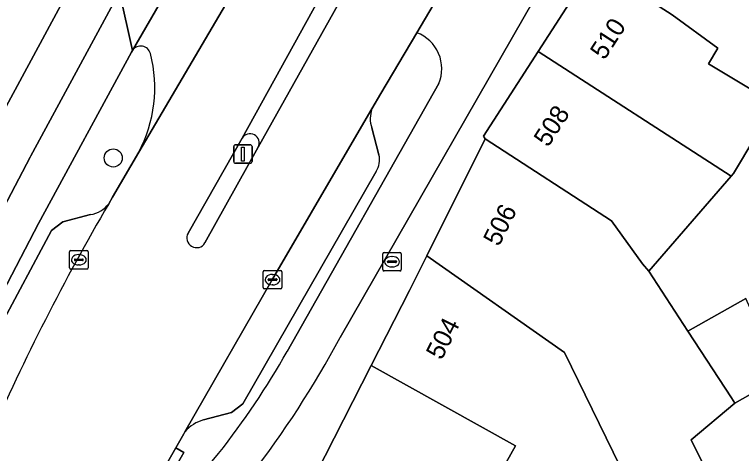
# Model space of a CAD drawing. Extents: x 162989 to 165008, y 383432 to 384338.
# Drawn here: x 163840.69 to 163879.92, y 384086.45 to 384110.15 of the extents above; entities that cross this region are included whole.
import ezdxf

# ---------------------------------------------------------------- set-up
doc = ezdxf.new("R2010")
doc.units = 0
for name, color, linetype in [('IMGEO_Boom', 7, 'Continuous'), ('IMGEO_Brandkraan', 7, 'Continuous'), ('IMGEO_Erf', 7, 'Continuous'), ('IMGEO_Fietspad_open', 7, 'Continuous'), ('IMGEO_Kolk', 7, 'Continuous'), ('IMGEO_Lichtmast', 7, 'Continuous'), ('IMGEO_Pand', 7, 'Continuous'), ('IMGEO_Pand_nummerreeks', 7, 'Continuous'), ('IMGEO_Parkeervlak_open', 7, 'Continuous'), ('IMGEO_Rijbaan_lokaal_gesloten', 7, 'Continuous'), ('IMGEO_Rijbaan_lokaal_open', 7, 'Continuous'), ('IMGEO_Verkeerseiland_open', 7, 'Continuous'), ('IMGEO_Voetpad_open', 7, 'Continuous')]:
    doc.layers.add(name, color=color, linetype=linetype)

msp = doc.modelspace()

# ---------------------------------------------------------------- linework, layer by layer
at = {"layer": 'IMGEO_Boom'}
msp.add_circle((163846.016, 384102.406), 0.489, dxfattribs=at)
at = {"layer": 'IMGEO_Brandkraan'}
for p, q in [((163860.56, 384096.377), (163860.56, 384097.229)), ((163860.635, 384097.303), (163861.487, 384097.303)), ((163861.561, 384097.229), (163861.561, 384096.377)), ((163860.819, 384096.797), (163860.819, 384096.809)), ((163861.257, 384096.76), (163860.859, 384096.76)), ((163860.862, 384096.846), (163861.26, 384096.846)), ((163861.048, 384097.083), (163861.073, 384097.083)), ((163861.303, 384096.809), (163861.303, 384096.797)), ((163861.071, 384096.523), (163861.046, 384096.523)), ((163861.487, 384096.303), (163860.635, 384096.303))]:
    msp.add_line(p, q, dxfattribs=at)
for points in [[(163860.56, 384096.377), (163860.56, 384097.229)], [(163860.635, 384097.303), (163861.487, 384097.303)], [(163861.561, 384097.229), (163861.561, 384096.377)], [(163861.487, 384096.303), (163860.635, 384096.303)]]:
    msp.add_lwpolyline(points, dxfattribs=at)
for centre, radius, start, end in [((163860.637, 384097.227), 0.0765, 91.552, 178.448), ((163860.637, 384097.227), 0.0765, 91.552, 178.448), ((163861.485, 384097.227), 0.0765, 1.552, 88.448), ((163861.485, 384097.227), 0.0765, 1.552, 88.448), ((163860.859, 384096.806), 0.0403, 85.8775, 175.7526), ((163860.856, 384096.796), 0.0366, 178.938, 274.7102), ((163861.26, 384096.803), 0.043, 264.8664, 352.4533), ((163861.264, 384096.808), 0.0386, 1.7309, 96.639), ((163860.637, 384096.379), 0.0765, 181.552, 268.448), ((163860.637, 384096.379), 0.0765, 181.552, 268.448), ((163861.485, 384096.379), 0.0765, 271.552, 358.448), ((163861.485, 384096.379), 0.0765, 271.552, 358.448)]:
    msp.add_arc(centre, radius, start, end, dxfattribs=at)
for centre, major_axis, ratio, start_param, end_param in [((163861.047, 384096.803), (-0.387, 0.002), 0.722429, 4.712389, 7.853982), ((163861.072, 384096.803), (-0.39, 0.002), 0.717154, 1.570796, 4.712389)]:
    msp.add_ellipse(centre, major_axis=major_axis, ratio=ratio, start_param=start_param, end_param=end_param, dxfattribs=at)
at = {"layer": 'IMGEO_Erf'}
for points in [[(163880.994, 384111.502), (163878.774, 384116.163), (163876.517, 384120.624), (163871.977, 384112.853), (163876.171, 384110.131), (163878.645, 384108.341), (163878.133, 384107.482), (163881.743, 384105.323), (163879.492, 384101.562), (163879.363, 384101.414), (163874.911, 384096.29), (163877.027, 384093.047), (163880.149, 384094.815)], [(163882.049, 384090.569), (163879.564, 384089.159), (163877.195, 384087.195), (163881.846, 384077.8)]]:
    msp.add_lwpolyline(points, dxfattribs=at)
at = {"layer": 'IMGEO_Fietspad_open'}
for points in [[(163858.262, 384092.719), (163870.014, 384113.204), (163876.697, 384123.662), (163880.797, 384129.62), (163884.94, 384135.639), (163890.116, 384142.65), (163886.926, 384141.93), (163880.31, 384132.681), (163877.756, 384129.074), (163877.678, 384128.954), (163873.799, 384123.243), (163873.714, 384123.118), (163868.266, 384114.374), (163867.368, 384112.852)], [(163864.451, 384112.652), (163862.396, 384109.163)], [(163835.957, 384087.299), (163841.986, 384098.868), (163846.999, 384108.122), (163847.05, 384108.21), (163846.359, 384111.374), (163841.571, 384102.524), (163841.529, 384102.444), (163833.769, 384087.617), (163830.002, 384076.297), (163825.723, 384065.107)], [(163863.578, 384106.421), (163855.398, 384091.956)]]:
    msp.add_lwpolyline(points, dxfattribs=at)
msp.add_lwpolyline([(163855.148, 384122.181), (163853.132, 384122.958), (163852.001, 384121.008), (163846.359, 384111.374), (163847.05, 384108.21)], close=True, dxfattribs=at)
for centre, radius, start, end in [((163861.689, 384107.232), 2.056, 336.7595, 69.8796), ((163811.105, 384117.957), 53.486, 322.2613, 331.8452), ((163816.689, 384113.95), 44.521, 321.8557, 330.3951)]:
    msp.add_arc(centre, radius, start, end, dxfattribs=at)
at = {"layer": 'IMGEO_Kolk'}
for p, q in [((163843.659, 384096.481), (163843.659, 384097.333)), ((163843.734, 384097.407), (163844.586, 384097.407)), ((163844.147, 384097.187), (163844.172, 384097.187)), ((163844.66, 384097.333), (163844.66, 384096.481)), ((163843.918, 384096.901), (163843.918, 384096.913)), ((163844.356, 384096.864), (163843.958, 384096.864)), ((163843.961, 384096.95), (163844.359, 384096.95)), ((163844.402, 384096.913), (163844.402, 384096.901)), ((163844.586, 384096.407), (163843.734, 384096.407)), ((163844.17, 384096.627), (163844.145, 384096.627)), ((163854.185, 384096.335), (163855.037, 384096.335)), ((163854.11, 384095.409), (163854.11, 384096.261)), ((163854.598, 384096.115), (163854.623, 384096.115)), ((163855.111, 384096.261), (163855.111, 384095.409)), ((163854.369, 384095.829), (163854.369, 384095.841)), ((163854.807, 384095.792), (163854.409, 384095.792)), ((163854.412, 384095.878), (163854.81, 384095.878)), ((163854.621, 384095.555), (163854.596, 384095.555)), ((163854.853, 384095.841), (163854.853, 384095.829)), ((163855.037, 384095.335), (163854.185, 384095.335))]:
    msp.add_line(p, q, dxfattribs=at)
for points in [[(163843.659, 384096.481), (163843.659, 384097.333)], [(163843.734, 384097.407), (163844.586, 384097.407)], [(163844.66, 384097.333), (163844.66, 384096.481)], [(163844.586, 384096.407), (163843.734, 384096.407)], [(163854.185, 384096.335), (163855.037, 384096.335)], [(163854.11, 384095.409), (163854.11, 384096.261)], [(163855.111, 384096.261), (163855.111, 384095.409)], [(163855.037, 384095.335), (163854.185, 384095.335)]]:
    msp.add_lwpolyline(points, dxfattribs=at)
for centre, radius, start, end in [((163843.736, 384097.331), 0.0765, 91.552, 178.448), ((163843.736, 384097.331), 0.0765, 91.552, 178.448), ((163844.584, 384097.331), 0.0765, 1.552, 88.448), ((163844.584, 384097.331), 0.0765, 1.552, 88.448), ((163843.958, 384096.91), 0.0403, 85.8775, 175.7526), ((163843.955, 384096.9), 0.0366, 178.938, 274.7102), ((163844.359, 384096.907), 0.043, 264.8664, 352.4533), ((163844.363, 384096.912), 0.0386, 1.7309, 96.639), ((163843.736, 384096.483), 0.0765, 181.552, 268.448), ((163843.736, 384096.483), 0.0765, 181.552, 268.448), ((163844.584, 384096.483), 0.0765, 271.552, 358.448), ((163844.584, 384096.483), 0.0765, 271.552, 358.448), ((163854.187, 384096.259), 0.0765, 91.552, 178.448), ((163854.187, 384096.259), 0.0765, 91.552, 178.448), ((163855.035, 384096.259), 0.0765, 1.552, 88.448), ((163855.035, 384096.259), 0.0765, 1.552, 88.448), ((163854.409, 384095.838), 0.0403, 85.8775, 175.7526), ((163854.406, 384095.828), 0.0366, 178.938, 274.7102), ((163854.81, 384095.835), 0.043, 264.8664, 352.4533), ((163854.814, 384095.84), 0.0386, 1.7309, 96.639), ((163854.187, 384095.411), 0.0765, 181.552, 268.448), ((163854.187, 384095.411), 0.0765, 181.552, 268.448), ((163855.035, 384095.411), 0.0765, 271.552, 358.448), ((163855.035, 384095.411), 0.0765, 271.552, 358.448)]:
    msp.add_arc(centre, radius, start, end, dxfattribs=at)
for centre, major_axis, ratio, start_param, end_param in [((163844.146, 384096.907), (-0.387, 0.002), 0.722429, 4.712389, 7.853982), ((163844.171, 384096.907), (-0.39, 0.002), 0.717154, 1.570796, 4.712389), ((163854.597, 384095.835), (-0.387, 0.002), 0.722429, 4.712389, 7.853982), ((163854.622, 384095.835), (-0.39, 0.002), 0.717154, 1.570796, 4.712389)]:
    msp.add_ellipse(centre, major_axis=major_axis, ratio=ratio, start_param=start_param, end_param=end_param, dxfattribs=at)
at = {"layer": 'IMGEO_Lichtmast'}
for p, q in [((163852.518, 384102.216), (163852.518, 384103.016)), ((163852.518, 384103.016), (163852.518, 384102.216)), ((163852.618, 384103.116), (163853.408, 384103.116)), ((163853.408, 384103.116), (163852.618, 384103.116)), ((163853.508, 384103.016), (163853.508, 384102.216)), ((163853.508, 384102.216), (163853.508, 384103.016)), ((163853.408, 384102.116), (163852.618, 384102.116)), ((163852.618, 384102.116), (163853.408, 384102.116))]:
    msp.add_line(p, q, dxfattribs=at)
msp.add_lwpolyline([(163852.938, 384102.991), (163853.088, 384102.991), (163853.088, 384102.241), (163852.938, 384102.241), (163852.938, 384102.991)], dxfattribs=at)
for centre, start, end in [((163852.618, 384103.016), 90, 180), ((163852.618, 384103.016), 90, 180), ((163853.408, 384103.016), 0, 90), ((163853.408, 384103.016), 360, 90), ((163852.618, 384102.216), 180, 270), ((163852.618, 384102.216), 180, 270), ((163853.408, 384102.216), 270, 0), ((163853.408, 384102.216), 270, 0)]:
    msp.add_arc(centre, 0.1, start, end, dxfattribs=at)
at = {"layer": 'IMGEO_Pand'}
for points in [[(163879.363, 384101.414), (163879.492, 384101.562), (163881.743, 384105.323), (163878.133, 384107.482), (163878.645, 384108.341), (163876.171, 384110.131), (163871.977, 384112.853), (163868.943, 384108.154)], [(163866.088, 384103.44), (163872.912, 384099.019), (163874.579, 384096.686), (163874.911, 384096.29), (163879.363, 384101.414), (163868.943, 384108.154), (163865.996, 384103.589)], [(163862.93, 384097.12), (163870.367, 384091.903), (163874.118, 384084.233), (163874.237, 384084.468), (163880.742, 384070.686), (163884.133, 384063.386), (163887.952, 384065.464), (163887.443, 384066.493), (163883.76, 384073.932), (163881.846, 384077.8), (163877.195, 384087.195), (163879.564, 384089.159), (163879.376, 384089.447), (163877.027, 384093.047), (163874.911, 384096.29), (163874.579, 384096.686), (163872.912, 384099.019), (163866.088, 384103.44)], [(163870.367, 384091.903), (163862.93, 384097.12), (163861.996, 384095.251), (163859.931, 384091.201), (163867.724, 384086.87), (163866.8, 384085.222), (163868.479, 384084.373), (163869.073, 384084.073), (163871.322, 384082.935), (163871.242, 384082.811), (163872.957, 384081.942), (163874.118, 384084.233)], [(163880.149, 384094.815), (163877.027, 384093.047), (163879.376, 384089.447), (163879.564, 384089.159), (163882.049, 384090.569), (163881.908, 384090.883)], [(163867.919, 384083.301), (163868.479, 384084.373), (163866.8, 384085.222), (163867.724, 384086.87), (163859.931, 384091.201), (163855.45, 384082.409), (163855.788, 384082.237), (163859.419, 384080.39), (163859.125, 384079.799), (163860.358, 384079.187), (163862.778, 384077.985), (163862.486, 384077.41), (163867.325, 384074.959), (163868.96, 384078.187), (163869.086, 384080.143), (163868.705, 384082.086)]]:
    msp.add_lwpolyline(points, close=True, dxfattribs=at)
at = {"layer": 'IMGEO_Parkeervlak_open'}
for points in [[(163859.978, 384105.056), (163858.788, 384103.032), (163854.613, 384095.853), (163849.885, 384087.626)], [(163860.355, 384102.58), (163859.962, 384104.033)], [(163850.895, 384088.264), (163852.398, 384088.66), (163853.004, 384089.123), (163860.207, 384101.678)], [(163844.795, 384099.349), (163843.293, 384098.955), (163842.69, 384098.481), (163839.842, 384093.19), (163835.518, 384084.093), (163835.459, 384083.328), (163835.942, 384081.7)]]:
    msp.add_lwpolyline(points, dxfattribs=at)
for centre, radius, start, end in [((163861.433, 384104.522), 1.55, 159.8302, 198.3777), ((163859.218, 384102.303), 1.17, 327.6856, 13.6783), ((163951.771, 384037.964), 122.782, 149.69013, 156.3498), ((163844.582, 384100.821), 1.487, 278.2421, 323.1492), ((163851.426, 384086.305), 2.03, 105.1637, 139.3961)]:
    msp.add_arc(centre, radius, start, end, dxfattribs=at)
at = {"layer": 'IMGEO_Rijbaan_lokaal_gesloten'}
for points in [[(163883.633, 384142.477), (163870.466, 384139.819), (163869.358, 384138.308), (163864.296, 384131.091), (163862.016, 384127.623), (163859.763, 384123.759), (163847.388, 384102.711), (163845.979, 384100.283), (163845.772, 384099.929)], [(163834.654, 384059.947), (163837.636, 384065.552), (163837.793, 384065.847), (163839.438, 384068.873), (163846.703, 384082.035), (163847.456, 384083.359), (163849.385, 384086.749), (163849.823, 384087.518), (163849.885, 384087.626), (163854.613, 384095.853), (163858.788, 384103.032), (163859.978, 384105.056), (163860.464, 384105.88), (163862.396, 384109.163), (163864.451, 384112.652), (163865.93, 384115.162), (163868.952, 384120.271), (163874.431, 384129.062), (163874.683, 384129.423), (163876.691, 384132.556), (163882.616, 384141.024)], [(163850.056, 384098.353), (163852.971, 384103.465), (163862.368, 384120.5), (163863.756, 384123.203), (163864.304, 384124.106), (163866.796, 384128.127), (163866.803, 384128.137), (163869.411, 384131.917), (163874.964, 384139.608)], [(163876.307, 384138.568), (163871.291, 384131.455), (163868.779, 384127.938), (163868.12, 384127.015), (163866.481, 384124.459), (163865.588, 384123.261), (163863.299, 384119.895), (163853.831, 384102.994), (163850.964, 384097.823)], [(163862.368, 384120.5), (163852.971, 384103.465)], [(163853.831, 384102.994), (163863.299, 384119.895)]]:
    msp.add_lwpolyline(points, dxfattribs=at)
for centre, radius, start, end in [((163853.399, 384103.226), 0.49, 331.8018, 150.7814), ((163951.771, 384037.964), 122.782, 149.69013, 156.3498), ((163850.511, 384098.089), 0.526, 149.8771, 329.5786)]:
    msp.add_arc(centre, radius, start, end, dxfattribs=at)
at = {"layer": 'IMGEO_Rijbaan_lokaal_open'}
for points in [[(163847.388, 384102.711), (163859.763, 384123.759)], [(163855.148, 384122.181), (163847.05, 384108.21)]]:
    msp.add_lwpolyline(points, dxfattribs=at)
for centre, radius, start, end in [((163847.499, 384107.9), 0.546, 15.5651, 145.3387), ((163840.878, 384106.194), 7.383, 331.8521, 14.5301)]:
    msp.add_arc(centre, radius, start, end, dxfattribs=at)
at = {"layer": 'IMGEO_Verkeerseiland_open'}
for points in [[(163862.396, 384109.163), (163860.464, 384105.88), (163859.978, 384105.056)], [(163847.05, 384108.21), (163846.999, 384108.122), (163841.986, 384098.868), (163835.957, 384087.299)], [(163855.398, 384091.956), (163863.578, 384106.421)], [(163859.962, 384104.033), (163860.355, 384102.58)], [(163852.971, 384103.465), (163850.056, 384098.353)], [(163850.964, 384097.823), (163853.831, 384102.994)], [(163845.772, 384099.929), (163845.979, 384100.283), (163847.388, 384102.711)], [(163860.207, 384101.678), (163853.004, 384089.123), (163852.398, 384088.66), (163850.895, 384088.264)], [(163835.942, 384081.7), (163835.459, 384083.328), (163835.518, 384084.093), (163839.842, 384093.19), (163842.69, 384098.481), (163843.293, 384098.955), (163844.795, 384099.349)], [(163849.885, 384087.626), (163849.823, 384087.518), (163849.385, 384086.749), (163849.819, 384086.502), (163847.89, 384083.112), (163847.456, 384083.359), (163846.703, 384082.035), (163839.438, 384068.873), (163839.851, 384068.648), (163848.601, 384082.726), (163851.703, 384086.452)]]:
    msp.add_lwpolyline(points, dxfattribs=at)
for centre, radius, start, end in [((163861.689, 384107.232), 2.056, 336.7595, 69.8796), ((163847.499, 384107.9), 0.546, 15.5651, 145.3387), ((163840.878, 384106.194), 7.383, 331.8521, 14.5301), ((163861.433, 384104.522), 1.55, 159.8302, 198.3777), ((163853.399, 384103.226), 0.49, 331.8018, 150.7814), ((163859.218, 384102.303), 1.17, 327.6856, 13.6783), ((163844.582, 384100.821), 1.487, 278.2421, 323.1492), ((163850.511, 384098.089), 0.526, 149.8771, 329.5786), ((163816.689, 384113.95), 44.521, 321.8557, 330.3951), ((163851.426, 384086.305), 2.03, 105.1637, 139.3961)]:
    msp.add_arc(centre, radius, start, end, dxfattribs=at)
at = {"layer": 'IMGEO_Voetpad_open'}
for points in [[(163844.546, 384060.544), (163843.746, 384060.938), (163844.414, 384062.211), (163840.91, 384064.16), (163841.041, 384064.396), (163842.579, 384067.157), (163842.429, 384067.258), (163847.399, 384074.635), (163851.988, 384081.446), (163854.481, 384079.751), (163855.788, 384082.237), (163855.45, 384082.409), (163859.931, 384091.201), (163861.996, 384095.251), (163862.93, 384097.12), (163866.088, 384103.44), (163865.996, 384103.589), (163868.943, 384108.154), (163871.977, 384112.853), (163876.517, 384120.624), (163879.586, 384125.813)], [(163876.697, 384123.662), (163870.014, 384113.204), (163858.262, 384092.719)], [(163845.14, 384114.307), (163839.604, 384104.048), (163833.039, 384091.042), (163827.304, 384079.681), (163823.683, 384072.507), (163822.343, 384069.959), (163821.36, 384068.226), (163821.507, 384068.122), (163824.405, 384066.034), (163819.835, 384058.771), (163818.285, 384059.918), (163817.775, 384059.146), (163810.967, 384045.208), (163810.741, 384045.3), (163809.212, 384042.588), (163809.104, 384042.631), (163804.861, 384033.884), (163796.988, 384017.276), (163789.265, 384000), (163788.336, 383997.923), (163787.048, 383994.75)], [(163839.75, 384104.35), (163839.604, 384104.048), (163845.14, 384114.307)], [(163825.723, 384065.107), (163830.002, 384076.297), (163833.769, 384087.617), (163841.529, 384102.444), (163841.571, 384102.524), (163846.359, 384111.374)]]:
    msp.add_lwpolyline(points, dxfattribs=at)
msp.add_lwpolyline([(163847.456, 384083.359), (163847.89, 384083.112), (163849.819, 384086.502), (163849.385, 384086.749)], close=True, dxfattribs=at)
msp.add_arc((163811.105, 384117.957), 53.486, 322.2613, 331.8452, dxfattribs=at)

# ---------------------------------------------------------------- texts
at = {"layer": 'IMGEO_Pand_nummerreeks'}
for s, rotation, p in [('510', 57.1509, (163872.521, 384107.648)), ('508', 57.1552, (163869.481, 384102.94)), ('506', 63.4488, (163866.827, 384097.581)), ('504', 63.1342, (163863.735, 384091.449))]:
    msp.add_text(s, height=1, rotation=rotation, dxfattribs=at).set_placement(p)

doc.saveas('drawing.dxf')
